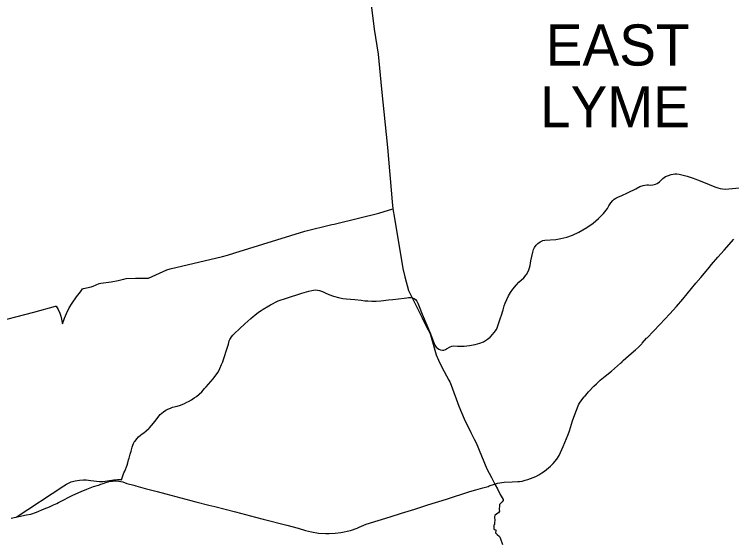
# Model space of a CAD drawing. Extents: x 0 to 2603, y -226 to 830.
# Drawn here: x 263.15 to 286.68, y 535.07 to 552.39 of the extents above; entities that cross this region are included whole.
import ezdxf

# ---------------------------------------------------------------- set-up
doc = ezdxf.new("R2010")
doc.units = 0
for name, color, linetype in [('CT_TSH_Map_Interstate_Roads', 7, 'Continuous'), ('CT_TSH_Map_Town_Limits', 7, 'Continuous'), ('CT_TSH_Map_Town_Text', 7, 'Continuous'), ('CT_TSH_Map_US_and_State_Routes', 7, 'Continuous')]:
    doc.layers.add(name, color=color, linetype=linetype)

msp = doc.modelspace()

# ---------------------------------------------------------------- linework, layer by layer
at = {"layer": 'CT_TSH_Map_Interstate_Roads'}
for points in [[(286.434, 544.66), (286.745, 545.016)], [(284.647, 542.569), (284.872, 542.807), (285.078, 543.05), (285.508, 543.571), (285.666, 543.761), (285.84, 543.968), (285.942, 544.092), (286.019, 544.182), (286.229, 544.424), (286.434, 544.66)], [(284.32, 542.223), (284.647, 542.569)], [(283.908, 541.784), (284.32, 542.223)], [(283.726, 541.588), (283.741, 541.607), (283.889, 541.767)], [(283.889, 541.767), (283.908, 541.784)], [(283.116, 541.043), (283.295, 541.194), (283.458, 541.339), (283.527, 541.393), (283.622, 541.482), (283.726, 541.588)], [(281.854, 539.852), (281.981, 540.008), (282.16, 540.199), (282.244, 540.279), (282.367, 540.391), (282.533, 540.524), (282.731, 540.693), (283.03, 540.951), (283.086, 541.001)], [(283.073, 541.001), (283.116, 541.043)], [(281.764, 539.747), (281.841, 539.852)], [(280.739, 537.579), (280.824, 537.667), (280.94, 537.806), (281.021, 537.922), (281.149, 538.224), (281.313, 538.612), (281.356, 538.73), (281.462, 539.062), (281.569, 539.353), (281.665, 539.603), (281.764, 539.747)], [(280.451, 537.352), (280.537, 537.415), (280.604, 537.462), (280.671, 537.516), (280.739, 537.579)], [(279.662, 537.07), (279.724, 537.075), (279.801, 537.088), (279.903, 537.113), (279.993, 537.138), (280.166, 537.201)], [(280.166, 537.201), (280.253, 537.242)], [(280.253, 537.242), (280.353, 537.293), (280.451, 537.352)], [(264.594, 536.381), (264.796, 536.482), (264.917, 536.545), (265.071, 536.623), (265.339, 536.744), (265.528, 536.821), (265.75, 536.905), (265.91, 536.957), (265.945, 536.969)], [(265.945, 536.969), (265.99, 536.983)], [(265.99, 536.983), (266.057, 537.007), (266.148, 537.044), (266.223, 537.065), (266.3, 537.079)], [(266.3, 537.079), (266.368, 537.089), (266.419, 537.091), (266.488, 537.091), (266.571, 537.083), (266.642, 537.071)], [(266.642, 537.071), (266.707, 537.057), (266.834, 537.013), (267.067, 536.952), (267.096, 536.943)], [(267.096, 536.943), (267.134, 536.933)], [(278.724, 536.933), (278.901, 536.991), (278.994, 537.018), (279.218, 537.048), (279.477, 537.061)], [(279.477, 537.061), (279.662, 537.07)], [(267.134, 536.933), (267.438, 536.845), (267.83, 536.745), (268.115, 536.67), (269.101, 536.411), (269.533, 536.298)], [(277.321, 536.497), (278.087, 536.74)], [(278.087, 536.74), (278.29, 536.801)], [(278.29, 536.801), (278.518, 536.868)], [(278.518, 536.868), (278.694, 536.908)], [(278.694, 536.908), (278.724, 536.933)], [(276.281, 536.171), (276.711, 536.306), (277.321, 536.497)], [(263.873, 536.072), (264.128, 536.172), (264.301, 536.244), (264.435, 536.304), (264.537, 536.352)], [(264.537, 536.352), (264.594, 536.381)], [(269.533, 536.298), (269.72, 536.253)], [(269.72, 536.253), (270.403, 536.075)], [(263.546, 535.978), (263.686, 536.007)], [(263.686, 536.007), (263.873, 536.072)], [(270.403, 536.075), (271.058, 535.906)], [(274.687, 535.673), (275.473, 535.919), (275.846, 536.038)], [(275.846, 536.038), (276.281, 536.171)], [(263.039, 535.875), (263.546, 535.978)], [(271.058, 535.906), (271.312, 535.837)], [(271.312, 535.837), (272.084, 535.64), (272.459, 535.547), (272.704, 535.465), (272.901, 535.42), (273.123, 535.379), (273.365, 535.366), (273.48, 535.363), (273.667, 535.375)], [(273.667, 535.375), (273.861, 535.398), (274.176, 535.468), (274.391, 535.541), (274.461, 535.571)], [(274.461, 535.571), (274.687, 535.673)]]:
    msp.add_lwpolyline(points, dxfattribs=at)
at = {"layer": 'CT_TSH_Map_Town_Limits'}
for points in [[(275.488, 563.338), (275.33, 561.688), (275.17, 560.802), (275.075, 559.97), (275.076, 558.97), (274.926, 558.218), (274.848, 557.249), (274.763, 556.916), (274.551, 555.215), (274.747, 553.593), (274.947, 551.897), (275.086, 551.086), (275.194, 549.939), (275.391, 548.023), (275.546, 546.245), (275.569, 546.015)], [(262.344, 542.248), (263.785, 542.623), (264.503, 542.816), (264.52, 542.821), (264.591, 542.715), (264.64, 542.592), (264.671, 542.494), (264.726, 542.241), (264.792, 542.43), (264.857, 542.585), (264.945, 542.763), (265.042, 542.917), (265.185, 543.123), (265.32, 543.288), (265.387, 543.386), (265.414, 543.396), (265.664, 543.457), (265.733, 543.48), (265.93, 543.561), (265.985, 543.577), (266.323, 543.621), (266.555, 543.663), (266.731, 543.704), (266.744, 543.709), (266.818, 543.726), (267.121, 543.737), (267.547, 543.74), (268.149, 544.016), (268.261, 544.046), (269.979, 544.446), (270.139, 544.489), (270.385, 544.57), (272.676, 545.278), (273.563, 545.493), (273.639, 545.51), (273.728, 545.529), (275.1, 545.867), (275.569, 546.015)], [(275.569, 546.015), (275.615, 545.706), (275.889, 544.053), (275.958, 543.778), (276.076, 543.334), (276.525, 542.435), (276.58, 542.317), (276.72, 542.044), (276.785, 541.911), (276.798, 541.879), (276.985, 541.222), (277.062, 541.055), (277.171, 540.82), (277.399, 540.399), (277.435, 540.337), (277.474, 540.226), (277.731, 539.538), (277.899, 539.127), (278.12, 538.679), (278.17, 538.591), (278.234, 538.462), (278.302, 538.341), (278.648, 537.485), (278.795, 537.201), (278.916, 536.967), (278.992, 536.83), (279.082, 536.652), (279.179, 536.478), (279.178, 536.445), (279.153, 536.409), (279.1, 536.357), (279.068, 536.314), (279.061, 536.282), (279.056, 536.157), (279.06, 536.097), (279.03, 536.041), (278.98, 536.015), (278.906, 535.954), (278.894, 535.913), (278.912, 535.781), (278.9, 535.738), (278.903, 535.666), (278.881, 535.639), (278.876, 535.536), (278.893, 535.505), (278.939, 535.486), (278.942, 535.464), (278.936, 535.391), (278.988, 535.331), (279.063, 535.27), (279.089, 535.227), (279.158, 535.013)]]:
    msp.add_lwpolyline(points, dxfattribs=at)
at = {"layer": 'CT_TSH_Map_US_and_State_Routes'}
for points in [[(284.422, 547.007), (284.508, 547.067), (284.601, 547.11), (284.689, 547.138), (284.764, 547.153), (284.815, 547.155), (284.884, 547.157), (284.959, 547.148), (285.221, 547.088), (285.386, 547.025)], [(284.031, 546.793), (284.094, 546.799), (284.175, 546.821), (284.234, 546.848), (284.31, 546.895), (284.381, 546.96), (284.422, 547.007)], [(285.386, 547.025), (285.499, 546.98)], [(285.499, 546.98), (285.552, 546.959)], [(285.552, 546.959), (285.753, 546.882)], [(285.753, 546.882), (286.125, 546.736), (286.226, 546.702), (286.304, 546.682), (286.378, 546.67)], [(283.052, 546.438), (283.284, 546.55), (283.535, 546.673), (283.665, 546.74), (283.772, 546.773), (283.829, 546.786), (283.897, 546.795)], [(283.897, 546.795), (283.952, 546.795), (284.031, 546.793)], [(286.378, 546.67), (286.466, 546.66), (286.588, 546.663), (286.938, 546.705), (287.149, 546.729)], [(281.925, 545.396), (282.134, 545.545), (282.31, 545.7), (282.47, 545.862), (282.601, 546.025), (282.65, 546.114), (282.713, 546.211), (282.775, 546.283), (282.824, 546.324), (282.884, 546.364)], [(282.884, 546.364), (282.968, 546.408), (283.052, 546.438)], [(280.915, 545.006), (281.071, 545.037), (281.266, 545.086), (281.452, 545.153), (281.663, 545.247), (281.925, 545.396)], [(280.315, 544.876), (280.4, 544.934), (280.486, 544.971), (280.554, 544.985), (280.915, 545.006)], [(280.047, 544.073), (280.07, 544.156), (280.085, 544.305), (280.153, 544.591), (280.176, 544.675), (280.21, 544.747), (280.261, 544.823), (280.315, 544.876)], [(279.945, 543.861), (279.988, 543.931), (280.027, 544.007), (280.047, 544.073)], [(279.359, 543.159), (279.42, 543.264), (279.5, 543.378), (279.618, 543.523), (279.699, 543.607), (279.858, 543.75), (279.933, 543.843), (279.945, 543.861)], [(272.071, 543.083), (272.577, 543.242), (272.81, 543.314), (272.912, 543.34), (272.965, 543.348), (273.027, 543.352)], [(273.027, 543.352), (273.089, 543.345), (273.153, 543.335), (273.186, 543.328), (273.252, 543.306), (273.348, 543.261), (273.466, 543.206), (273.616, 543.15), (273.782, 543.106), (273.927, 543.077), (274.028, 543.062), (274.317, 543.044), (274.524, 543.019)], [(271.548, 542.868), (271.797, 543), (272.071, 543.083)], [(274.524, 543.019), (274.642, 542.999), (274.747, 542.994), (274.875, 542.986), (275.013, 542.99), (275.169, 543.001), (275.422, 543.029), (275.569, 543.045), (275.936, 543.088), (276.026, 543.099), (276.082, 543.109), (276.152, 543.108), (276.211, 543.092), (276.258, 543.072), (276.304, 543.038), (276.348, 542.989), (276.386, 542.92), (276.43, 542.814), (276.53, 542.559), (276.795, 541.909), (276.875, 541.708), (276.919, 541.599), (276.946, 541.538), (276.988, 541.479), (277.025, 541.447), (277.074, 541.416), (277.126, 541.394), (277.194, 541.383), (277.241, 541.384), (277.29, 541.402), (277.319, 541.418)], [(279.179, 542.7), (279.217, 542.83), (279.248, 542.917), (279.299, 543.044), (279.359, 543.159)], [(271.306, 542.722), (271.491, 542.836)], [(271.491, 542.836), (271.548, 542.868)], [(271.042, 542.529), (271.16, 542.62), (271.25, 542.683), (271.306, 542.722)], [(279.116, 542.494), (279.179, 542.7)], [(270.706, 542.246), (270.907, 542.419)], [(270.907, 542.419), (270.98, 542.478)], [(270.98, 542.478), (271.042, 542.529)], [(278.602, 541.692), (278.67, 541.738), (278.757, 541.807), (278.837, 541.888), (278.891, 541.954), (278.959, 542.059), (278.985, 542.106), (279.11, 542.471), (279.116, 542.494)], [(270.375, 541.929), (270.529, 542.08), (270.706, 542.246)], [(270.27, 541.816), (270.315, 541.868), (270.375, 541.929)], [(270.186, 541.635), (270.199, 541.682), (270.218, 541.725), (270.237, 541.765), (270.27, 541.816)], [(277.774, 541.511), (277.903, 541.512), (278.083, 541.53), (278.264, 541.567), (278.42, 541.611), (278.536, 541.655)], [(278.536, 541.655), (278.602, 541.692)], [(270.007, 541.068), (270.134, 541.449), (270.173, 541.574), (270.186, 541.635)], [(277.319, 541.418), (277.448, 541.489), (277.502, 541.515), (277.552, 541.525), (277.683, 541.512), (277.774, 541.511)], [(269.699, 540.478), (269.76, 540.556), (269.83, 540.662), (269.893, 540.776), (269.947, 540.904), (269.986, 540.994), (270.007, 541.068)], [(269.441, 540.177), (269.668, 540.436), (269.699, 540.478)], [(268.862, 539.699), (268.96, 539.755), (269.05, 539.813), (269.12, 539.865), (269.21, 539.937), (269.296, 540.016)], [(269.296, 540.016), (269.391, 540.118), (269.441, 540.177)], [(268.273, 539.482), (268.336, 539.505), (268.486, 539.546), (268.598, 539.581), (268.73, 539.634), (268.804, 539.669), (268.862, 539.699)], [(267.852, 539.176), (267.936, 539.269), (268.037, 539.354), (268.119, 539.411), (268.18, 539.446), (268.273, 539.482)], [(267.398, 538.668), (267.467, 538.737), (267.557, 538.807), (267.582, 538.833), (267.711, 538.987), (267.798, 539.099), (267.852, 539.176)], [(267.095, 538.382), (267.107, 538.4), (267.162, 538.474), (267.218, 538.533), (267.288, 538.592), (267.342, 538.631), (267.398, 538.668)], [(267.058, 538.315), (267.095, 538.382)], [(266.914, 537.837), (266.949, 537.971), (266.981, 538.07), (267.011, 538.196), (267.034, 538.265), (267.058, 538.315)], [(266.769, 537.415), (266.846, 537.605), (266.87, 537.685)], [(266.87, 537.685), (266.897, 537.78)], [(266.897, 537.78), (266.914, 537.837)], [(266.745, 537.357), (266.769, 537.415)], [(266.658, 537.125), (266.745, 537.357)], [(263.206, 535.909), (264.767, 536.934), (264.859, 536.991)], [(264.859, 536.991), (265.015, 537.06)], [(265.015, 537.06), (265.146, 537.099)], [(265.146, 537.099), (265.29, 537.122)], [(265.29, 537.122), (265.419, 537.128), (265.505, 537.125), (265.655, 537.103), (265.942, 537.076)], [(265.942, 537.076), (266.055, 537.077), (266.124, 537.082), (266.412, 537.124)], [(266.412, 537.124), (266.528, 537.141), (266.587, 537.139), (266.625, 537.135), (266.658, 537.125)]]:
    msp.add_lwpolyline(points, dxfattribs=at)

# ---------------------------------------------------------------- texts
at = {"layer": 'CT_TSH_Map_Town_Text'}
for s, p in [('EAST', (280.581, 550.708)), ('LYME', (280.391, 548.683))]:
    msp.add_text(s, height=1.35, dxfattribs=at).set_placement(p)

doc.saveas('drawing.dxf')
